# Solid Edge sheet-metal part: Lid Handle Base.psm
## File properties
Author: m_hel
Template: Iso Metric Sheet Metal.psm
Last saved by: m_hel
Revision: 5
Application: Solid Edge
Accuracy: 0,990
Material Thickness: 0,20 cm
Bend Radius: 0,10 cm
Relief Width: 0,10 cm
Relief Length: 0,00 cm
Neutral Factor: 0,330
Minimum Arc Length: 0,01 cm
Deviational Tolerance: 0,01 cm
Username: m_hel
Material: Chrome
Face Style: Chrome
Fill Style: Normal
Virtual Style: Normal
Grouping: Uncategorized
LibraryName: Custom Materials
Coef. of Thermal Exp: 0.0
Thermal Conductivity: 0.0
Specific Heat: 0.0
Modulus of Elasticity: 0.0
Poisson's Ratio: 0.0
Yield Stress: 0.0
Ultimate Stress: 0.0
Elongation: 0.0
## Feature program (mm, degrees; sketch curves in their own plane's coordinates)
base tab "unnamed BaseTab 1"
dimple "Dimple_1"
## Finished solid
Body 1: solid body, 53 faces, 122 edges, 72 vertices.
  Faces by surface: cylinder 25, torus 16, plane 12
  Edges by curve: circle 74, line 48
Bounding box of the edges (mm; curved faces can reach further): 80.000 x 80.000 x 17.000, from (-40, -40, -17) to (40, 40, 0).
Cylindrical faces by radius (mm): R0.2 x6, R2 x8, R2.2 x6, R30 x2, R32 x2, R40 x1
Toroidal faces (ring radius, tube radius in mm): R0.2 r2 x6, R2.2 r2 x6, R30 r2 x2, R32 r2 x2
Planar faces by outward normal: +x 2, +y 2, +z 2, -x 2, -y 2, -z 2
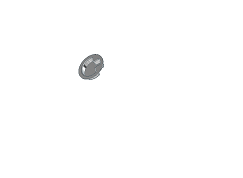
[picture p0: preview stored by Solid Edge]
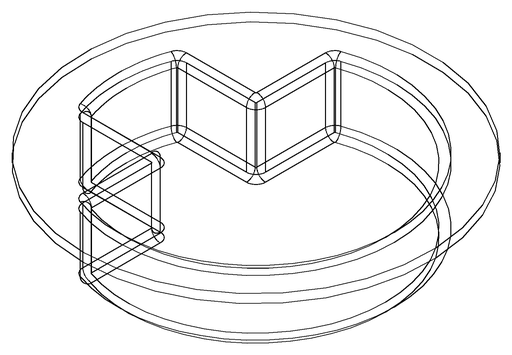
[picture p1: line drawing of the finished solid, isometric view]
